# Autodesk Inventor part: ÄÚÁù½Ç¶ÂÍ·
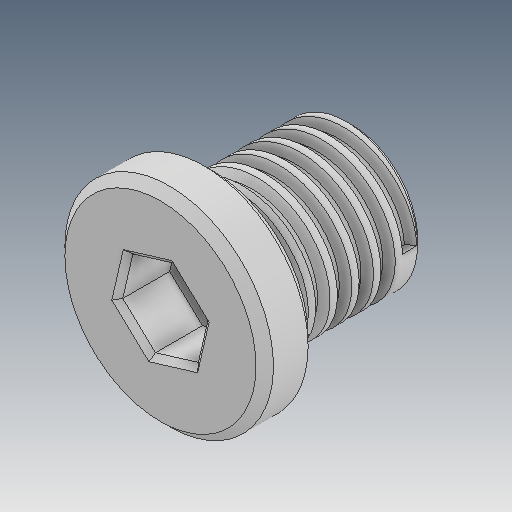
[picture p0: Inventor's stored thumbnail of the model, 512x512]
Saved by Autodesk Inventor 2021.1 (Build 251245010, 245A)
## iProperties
Created: 2015-08
Part Number: ÄÚÁù½Ç¶ÂÍ·
Material: Ogólny
Document SubType Name: Modeling
Designer: user
Density: 1 g/cm^3
Appearance: Domyślna
Author: user
Revision Number: ÈÎºÎ
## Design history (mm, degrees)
feature "ÇÐ³ý-É¨Ãè1"
node "Bryła1"
